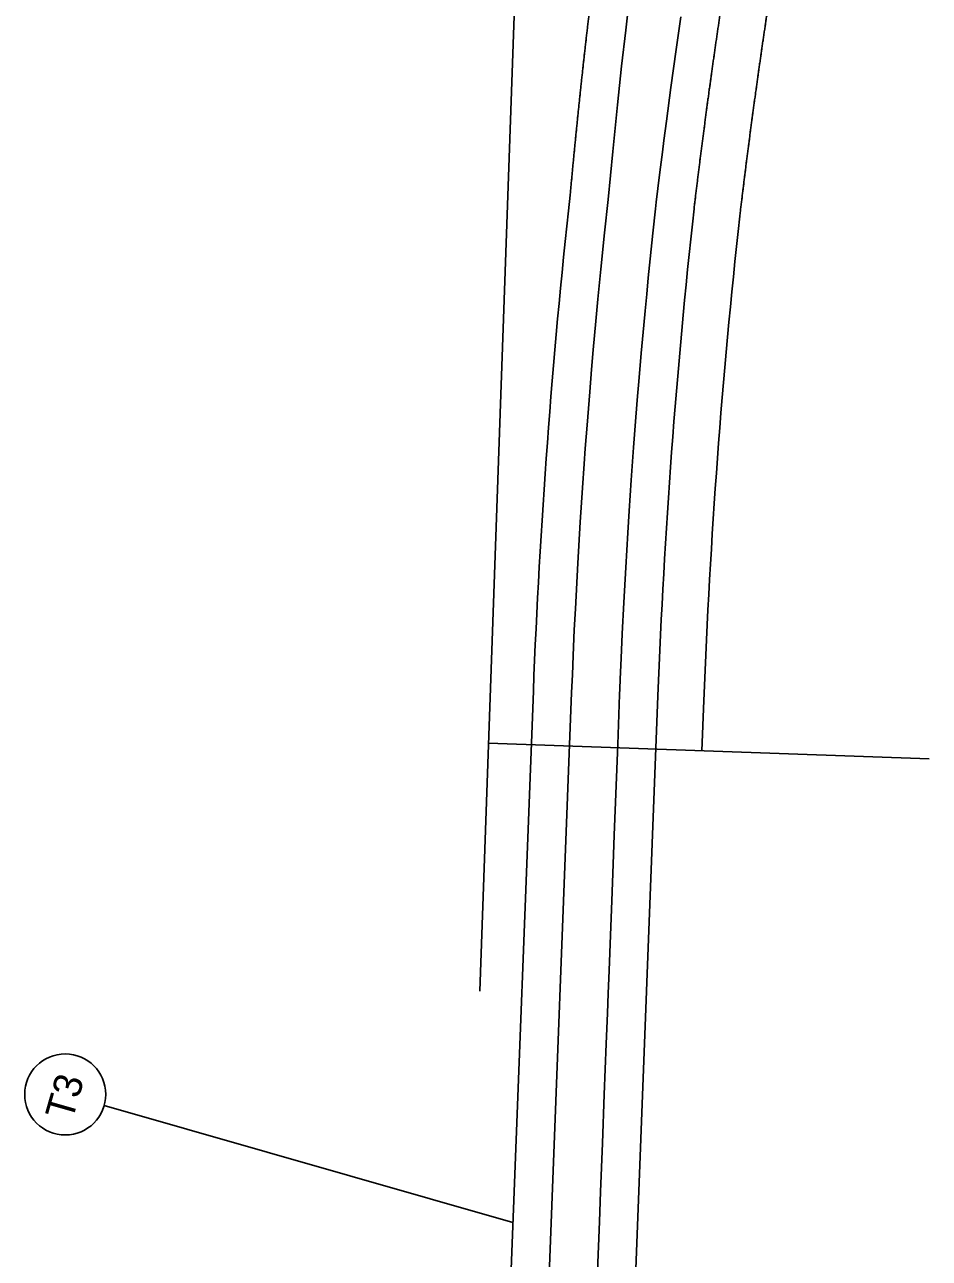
# Model space of a CAD drawing. Extents: x 1657109 to 2100937, y 684916 to 883211.
# Drawn here: x 2097595.1 to 2097896.4, y 688340.2 to 688751.2 of the extents above; entities that cross this region are included whole.
import ezdxf

# ---------------------------------------------------------------- set-up
doc = ezdxf.new("R2010")
doc.units = 0
for name, color, linetype in [('Prop CMT Pvmt Gravel', 7, 'Continuous'), ('Prop EOT', 7, 'Continuous'), ('Prop Sign E Chevron Right', 7, 'Continuous'), ('Scratch_Level_7', 7, 'Continuous')]:
    doc.layers.add(name, color=color, linetype=linetype)

msp = doc.modelspace()

# ---------------------------------------------------------------- linework, layer by layer
at = {"layer": 'Prop CMT Pvmt Gravel'}
msp.add_line((2097757.72, 688352.13), (2097621.6, 688391.1), dxfattribs=at)
msp.add_circle((2097608.62, 688394.82), 13.5, dxfattribs=at)
at = {"layer": 'Prop EOT'}
for p, q in [((2097705.89, 687000.49), (2097764.51, 688529.18)), ((2097747.36, 686998.9), (2097805.98, 688527.59))]:
    msp.add_line(p, q, dxfattribs=at)
for radius in [2320.75, 2279.25]:
    msp.add_arc((2100083.56, 688440.25), radius, 173.71336, 177.8037, dxfattribs=at)
for points in [[(2097826.17, 688751.22), (2097826.29, 688752.05), (2097826.41, 688752.88), (2097826.54, 688753.7), (2097826.66, 688754.53), (2097826.78, 688755.36), (2097826.9, 688756.19), (2097827.03, 688757.01), (2097827.15, 688757.84), (2097827.28, 688758.67), (2097827.4, 688759.5), (2097827.52, 688760.32), (2097827.65, 688761.15), (2097827.77, 688761.98), (2097827.9, 688762.81), (2097828.03, 688763.63), (2097828.15, 688764.46), (2097828.28, 688765.29), (2097828.4, 688766.11), (2097828.53, 688766.94), (2097828.66, 688767.77), (2097828.79, 688768.6), (2097828.91, 688769.42), (2097829.04, 688770.25), (2097829.17, 688771.08), (2097829.3, 688771.9), (2097829.43, 688772.73), (2097829.56, 688773.56), (2097829.69, 688774.38), (2097829.82, 688775.21), (2097829.95, 688776.04), (2097830.08, 688776.86), (2097830.21, 688777.69), (2097830.34, 688778.52), (2097830.47, 688779.34), (2097830.61, 688780.17), (2097830.74, 688780.99), (2097830.87, 688781.82), (2097831, 688782.65), (2097831.14, 688783.47), (2097831.27, 688784.3), (2097831.4, 688785.12), (2097831.54, 688785.95), (2097831.67, 688786.78), (2097831.81, 688787.6), (2097831.94, 688788.43), (2097832.08, 688789.25), (2097832.21, 688790.08), (2097832.35, 688790.9), (2097832.48, 688791.73), (2097832.62, 688792.56), (2097832.76, 688793.38), (2097832.9, 688794.21), (2097833.03, 688795.03), (2097833.17, 688795.86), (2097833.31, 688796.68), (2097833.45, 688797.51), (2097833.58, 688798.33), (2097833.72, 688799.16), (2097833.86, 688799.98), (2097834, 688800.81), (2097834.14, 688801.63), (2097834.28, 688802.46), (2097834.42, 688803.28), (2097834.56, 688804.11), (2097834.7, 688804.93), (2097834.85, 688805.76), (2097834.99, 688806.58), (2097835.13, 688807.4), (2097835.27, 688808.23), (2097835.41, 688809.05), (2097835.56, 688809.88), (2097835.7, 688810.7), (2097835.84, 688811.53), (2097835.99, 688812.35)], [(2097776.76, 688694.37), (2097776.84, 688695.22), (2097776.92, 688696.07), (2097777, 688696.92), (2097777.08, 688697.77), (2097777.15, 688698.62), (2097777.23, 688699.47), (2097777.31, 688700.32), (2097777.39, 688701.16), (2097777.47, 688702.01), (2097777.55, 688702.86), (2097777.63, 688703.71), (2097777.71, 688704.56), (2097777.79, 688705.41), (2097777.87, 688706.26), (2097777.96, 688707.1), (2097778.04, 688707.95), (2097778.12, 688708.8), (2097778.2, 688709.65), (2097778.29, 688710.5), (2097778.37, 688711.35), (2097778.45, 688712.19), (2097778.54, 688713.04), (2097778.62, 688713.89), (2097778.71, 688714.74), (2097778.79, 688715.59), (2097778.87, 688716.44), (2097778.96, 688717.28), (2097779.05, 688718.13), (2097779.13, 688718.98), (2097779.22, 688719.83), (2097779.3, 688720.68), (2097779.39, 688721.53), (2097779.48, 688722.37), (2097779.57, 688723.22), (2097779.65, 688724.07), (2097779.74, 688724.92), (2097779.83, 688725.77), (2097779.92, 688726.61), (2097780.01, 688727.46), (2097780.1, 688728.31), (2097780.19, 688729.16), (2097780.28, 688730.01), (2097780.37, 688730.85), (2097780.46, 688731.7), (2097780.55, 688732.55), (2097780.64, 688733.4), (2097780.73, 688734.24), (2097780.82, 688735.09), (2097780.92, 688735.94), (2097781.01, 688736.79), (2097781.1, 688737.63), (2097781.2, 688738.48), (2097781.29, 688739.33), (2097781.38, 688740.18), (2097781.48, 688741.02), (2097781.57, 688741.87), (2097781.67, 688742.72), (2097781.76, 688743.57), (2097781.86, 688744.41), (2097781.95, 688745.26), (2097782.05, 688746.11), (2097782.14, 688746.96), (2097782.24, 688747.8), (2097782.34, 688748.65), (2097782.44, 688749.5), (2097782.53, 688750.35), (2097782.63, 688751.19), (2097782.73, 688752.04), (2097782.83, 688752.89), (2097782.93, 688753.73), (2097783.03, 688754.58), (2097783.12, 688755.43), (2097783.22, 688756.27), (2097783.32, 688757.12)], [(2097818.02, 688689.83), (2097818.11, 688690.66), (2097818.21, 688691.49), (2097818.31, 688692.32), (2097818.41, 688693.15), (2097818.51, 688693.98), (2097818.61, 688694.82), (2097818.72, 688695.65), (2097818.82, 688696.48), (2097818.92, 688697.31), (2097819.02, 688698.14), (2097819.12, 688698.97), (2097819.22, 688699.8), (2097819.33, 688700.63), (2097819.43, 688701.46), (2097819.53, 688702.29), (2097819.64, 688703.12), (2097819.74, 688703.95), (2097819.85, 688704.78), (2097819.95, 688705.61), (2097820.05, 688706.44), (2097820.16, 688707.27), (2097820.27, 688708.1), (2097820.37, 688708.93), (2097820.48, 688709.77), (2097820.58, 688710.6), (2097820.69, 688711.43), (2097820.8, 688712.26), (2097820.9, 688713.09), (2097821.01, 688713.92), (2097821.12, 688714.75), (2097821.23, 688715.58), (2097821.34, 688716.41), (2097821.45, 688717.23), (2097821.56, 688718.06), (2097821.66, 688718.89), (2097821.77, 688719.72), (2097821.88, 688720.55), (2097821.99, 688721.38), (2097822.11, 688722.21), (2097822.22, 688723.04), (2097822.33, 688723.87), (2097822.44, 688724.7), (2097822.55, 688725.53), (2097822.66, 688726.36), (2097822.78, 688727.19), (2097822.89, 688728.02), (2097823, 688728.85), (2097823.11, 688729.68), (2097823.23, 688730.51), (2097823.34, 688731.34), (2097823.46, 688732.16), (2097823.57, 688732.99), (2097823.69, 688733.82), (2097823.8, 688734.65), (2097823.92, 688735.48), (2097824.03, 688736.31), (2097824.15, 688737.14), (2097824.27, 688737.97), (2097824.38, 688738.79), (2097824.5, 688739.62), (2097824.62, 688740.45), (2097824.73, 688741.28), (2097824.85, 688742.11), (2097824.97, 688742.94), (2097825.09, 688743.77), (2097825.21, 688744.59), (2097825.33, 688745.42), (2097825.45, 688746.25), (2097825.57, 688747.08), (2097825.69, 688747.91), (2097825.81, 688748.74), (2097825.93, 688749.56), (2097826.05, 688750.39), (2097826.17, 688751.22)]]:
    msp.add_spline(points, degree=3, dxfattribs=at)
at = {"layer": 'Prop Sign E Chevron Right'}
for p, q in [((2097746.67, 688429.22), (2097766.87, 689000.21)), ((2097820.63, 688509.33), (2097821.27, 688526)), ((2097749.59, 688511.85), (2097896.37, 688506.65))]:
    msp.add_line(p, q, dxfattribs=at)
msp.add_arc((2100086.86, 688439.11), 2267.25, 173.71336, 177.8037, dxfattribs=at)
for points in [[(2097841.35, 688748.45), (2097841.48, 688749.27), (2097841.6, 688750.09), (2097841.72, 688750.92), (2097841.84, 688751.74), (2097841.96, 688752.56), (2097842.09, 688753.39), (2097842.21, 688754.21), (2097842.33, 688755.03), (2097842.45, 688755.86), (2097842.58, 688756.68), (2097842.7, 688757.5), (2097842.83, 688758.33), (2097842.95, 688759.15), (2097843.08, 688759.97), (2097843.2, 688760.79), (2097843.33, 688761.62), (2097843.45, 688762.44), (2097843.58, 688763.26), (2097843.71, 688764.09), (2097843.83, 688764.91), (2097843.96, 688765.73), (2097844.09, 688766.55), (2097844.21, 688767.38), (2097844.34, 688768.2), (2097844.47, 688769.02), (2097844.6, 688769.84), (2097844.73, 688770.67), (2097844.86, 688771.49), (2097844.99, 688772.31), (2097845.12, 688773.13), (2097845.25, 688773.95), (2097845.38, 688774.78), (2097845.51, 688775.6), (2097845.64, 688776.42), (2097845.77, 688777.24), (2097845.9, 688778.06), (2097846.03, 688778.89), (2097846.16, 688779.71), (2097846.3, 688780.53), (2097846.43, 688781.35), (2097846.56, 688782.17), (2097846.7, 688782.99), (2097846.83, 688783.82), (2097846.96, 688784.64), (2097847.1, 688785.46), (2097847.23, 688786.28), (2097847.37, 688787.1), (2097847.5, 688787.92), (2097847.64, 688788.74), (2097847.77, 688789.56), (2097847.91, 688790.39), (2097848.05, 688791.21), (2097848.18, 688792.03), (2097848.32, 688792.85), (2097848.46, 688793.67), (2097848.6, 688794.49), (2097848.73, 688795.31), (2097848.87, 688796.13), (2097849.01, 688796.95), (2097849.15, 688797.77), (2097849.29, 688798.59), (2097849.43, 688799.41), (2097849.57, 688800.23), (2097849.71, 688801.05), (2097849.85, 688801.87), (2097849.99, 688802.7), (2097850.13, 688803.52), (2097850.27, 688804.34), (2097850.41, 688805.16), (2097850.55, 688805.98), (2097850.7, 688806.8), (2097850.84, 688807.62), (2097850.98, 688808.44), (2097851.12, 688809.26)], [(2097833.24, 688687.38), (2097833.34, 688688.21), (2097833.44, 688689.03), (2097833.54, 688689.86), (2097833.64, 688690.69), (2097833.74, 688691.51), (2097833.84, 688692.34), (2097833.94, 688693.17), (2097834.04, 688693.99), (2097834.14, 688694.82), (2097834.24, 688695.65), (2097834.34, 688696.47), (2097834.44, 688697.3), (2097834.55, 688698.12), (2097834.65, 688698.95), (2097834.75, 688699.78), (2097834.85, 688700.6), (2097834.96, 688701.43), (2097835.06, 688702.26), (2097835.17, 688703.08), (2097835.27, 688703.91), (2097835.37, 688704.73), (2097835.48, 688705.56), (2097835.59, 688706.38), (2097835.69, 688707.21), (2097835.8, 688708.04), (2097835.9, 688708.86), (2097836.01, 688709.69), (2097836.12, 688710.51), (2097836.22, 688711.34), (2097836.33, 688712.16), (2097836.44, 688712.99), (2097836.55, 688713.82), (2097836.65, 688714.64), (2097836.76, 688715.47), (2097836.87, 688716.29), (2097836.98, 688717.12), (2097837.09, 688717.94), (2097837.2, 688718.77), (2097837.31, 688719.59), (2097837.42, 688720.42), (2097837.53, 688721.24), (2097837.64, 688722.07), (2097837.75, 688722.89), (2097837.87, 688723.72), (2097837.98, 688724.54), (2097838.09, 688725.37), (2097838.2, 688726.19), (2097838.32, 688727.02), (2097838.43, 688727.84), (2097838.54, 688728.67), (2097838.66, 688729.49), (2097838.77, 688730.32), (2097838.88, 688731.14), (2097839, 688731.97), (2097839.11, 688732.79), (2097839.23, 688733.61), (2097839.34, 688734.44), (2097839.46, 688735.26), (2097839.58, 688736.09), (2097839.69, 688736.91), (2097839.81, 688737.74), (2097839.93, 688738.56), (2097840.04, 688739.38), (2097840.16, 688740.21), (2097840.28, 688741.03), (2097840.4, 688741.86), (2097840.52, 688742.68), (2097840.64, 688743.5), (2097840.75, 688744.33), (2097840.87, 688745.15), (2097840.99, 688745.98), (2097841.11, 688746.8), (2097841.23, 688747.62), (2097841.35, 688748.45)]]:
    msp.add_spline(points, degree=3, dxfattribs=at)
at = {"layer": 'Scratch_Level_7'}
for points in [[(2097769.37, 688323.09), (2097777.25, 688528.7), (2097777.49, 688534.63), (2097777.76, 688541.1), (2097778.15, 688549.6), (2097778.49, 688556.55), (2097779.31, 688571.76), (2097780.13, 688585.49), (2097780.88, 688596.89), (2097781.44, 688604.88), (2097781.81, 688609.99), (2097782.4, 688617.83), (2097783.28, 688628.9), (2097783.91, 688636.35), (2097784.47, 688642.87), (2097785.34, 688652.49), (2097786.03, 688659.8), (2097787, 688669.74), (2097788.25, 688681.91), (2097789.44, 688692.98), (2097790.95, 688709.01), (2097792.52, 688724.54), (2097793.9, 688737.41), (2097795.26, 688749.39), (2097795.96, 688755.38)], [(2097813.66, 688753.81), (2097813.22, 688750.77), (2097812.64, 688746.78), (2097812.1, 688742.98), (2097810.33, 688730.25), (2097808.82, 688719.02), (2097808, 688712.68), (2097807.5, 688708.76), (2097806.66, 688702.1), (2097805.99, 688696.59), (2097805.44, 688692.08), (2097805.19, 688689.85), (2097804.32, 688681.77), (2097803.43, 688673.18), (2097802.79, 688666.82), (2097802.26, 688661.45), (2097801.72, 688655.87), (2097801.28, 688651.1), (2097800.44, 688641.76), (2097799.62, 688632.33), (2097799.22, 688627.46), (2097798.65, 688620.4), (2097797.88, 688610.38), (2097797.1, 688599.51), (2097796.41, 688589.27), (2097795.94, 688581.94), (2097795.25, 688570.34), (2097794.62, 688558.75), (2097794.11, 688548.26), (2097793.74, 688540.19), (2097793.44, 688533.2), (2097793.32, 688529.98), (2097793.24, 688528.08), (2097792.6, 688511.39), (2097792.08, 688497.75), (2097791.45, 688481.24), (2097791.07, 688471.48), (2097790.6, 688459.26), (2097790.17, 688447.84), (2097789.72, 688436.14), (2097789.42, 688428.4), (2097789.17, 688421.88), (2097788.78, 688411.71), (2097788.13, 688394.83), (2097787.51, 688378.56), (2097786.89, 688362.41), (2097786.51, 688352.49), (2097785.88, 688335.98)]]:
    msp.add_lwpolyline(points, dxfattribs=at)

# ---------------------------------------------------------------- texts
at = {"layer": 'Prop CMT Pvmt Gravel'}
msp.add_text('T3', height=9.45, rotation=74.0259, dxfattribs=at).set_placement((2097610.93, 688385.71))

doc.saveas('drawing.dxf')
